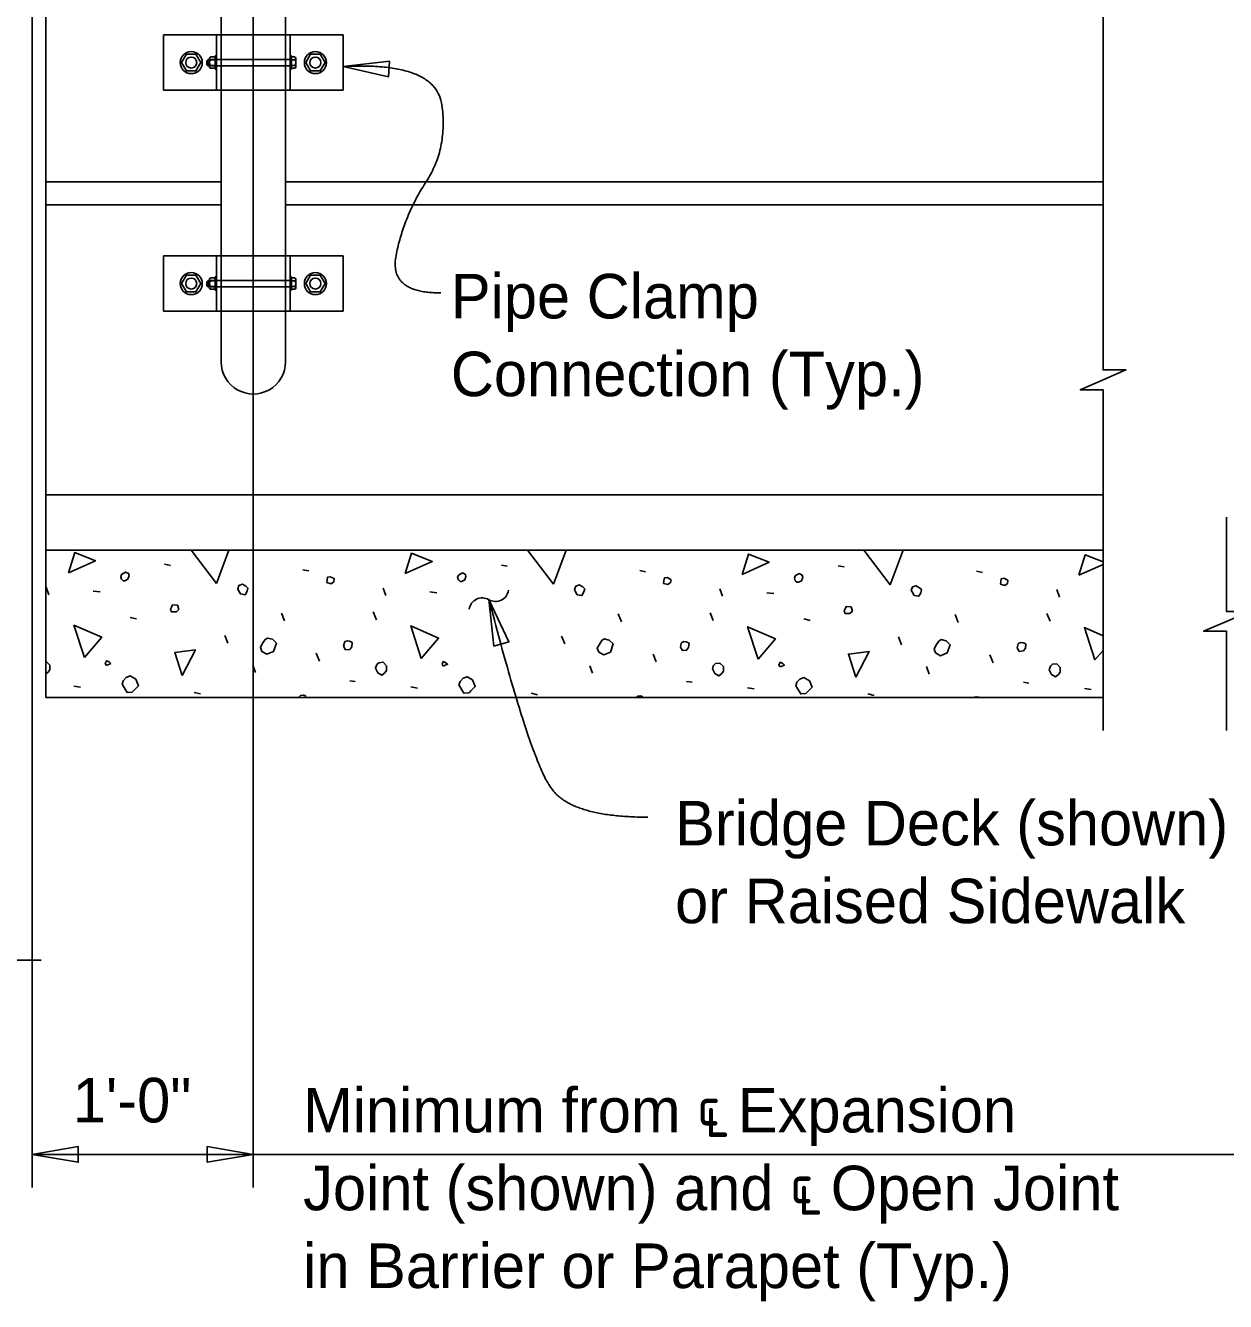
# Model space of a CAD drawing. Extents: x 0 to 41.1, y 0 to 25.9.
# Drawn here: x 23.58 to 29.01, y 11.16 to 16.93 of the extents above; entities that cross this region are included whole.
import ezdxf

# ---------------------------------------------------------------- set-up
doc = ezdxf.new("R2010")
doc.units = 0
for name, color, linetype in [('CL_Major', 7, 'Continuous'), ('Dimension', 7, 'Continuous'), ('Miscellaneous', 7, 'Continuous'), ('SteelMisc', 7, 'Continuous'), ('SteelMisc_h', 7, 'Continuous'), ('SupstrConc', 7, 'Continuous'), ('SupstrConc_h', 7, 'Continuous'), ('TextStructures', 7, 'Continuous')]:
    doc.layers.add(name, color=color, linetype=linetype)

msp = doc.modelspace()

# ---------------------------------------------------------------- linework, layer by layer
at = {"layer": 'CL_Major'}
for p, q in [((24.6151, 11.6734), (24.6151, 25.0052)), ((23.6151, 11.6734), (23.6151, 17.2313))]:
    msp.add_line(p, q, dxfattribs=at)
at = {"layer": 'Dimension'}
msp.add_line((23.6151, 11.8234), (29.4153, 11.8234), dxfattribs=at)
for points in [[(28.4596, 17.2246), (28.4596, 15.3737), (28.5629, 15.3737), (28.4596, 15.3287), (28.3562, 15.2837), (28.4596, 15.2837), (28.4596, 13.7412)], [(29.0176, 14.7079), (29.0176, 14.2808), (29.1209, 14.2808), (29.0176, 14.2358), (28.9142, 14.1908), (29.0176, 14.1908), (29.0176, 13.7412)], [(23.6547, 12.7032), (22.9577, 12.7032), (22.9577, 12.587), (22.8583, 12.812), (22.8583, 12.7032), (22.2031, 12.7032)]]:
    msp.add_lwpolyline(points, dxfattribs=at)
for points in [[(25.0211, 16.7461), (25.2271, 16.6998), (25.2309, 16.7703)], [(25.6811, 14.3341), (25.7034, 14.1241), (25.7713, 14.1431)], [(23.6151, 11.8235), (23.8234, 11.7882), (23.8234, 11.8588)], [(24.6151, 11.8235), (24.4069, 11.8588), (24.4069, 11.7882)]]:
    msp.add_lwpolyline(points, close=True, dxfattribs=at)
for centre, start, end in [((25.6504, 14.2822), 59.84335, 171.57057), ((25.7103, 14.3853), 239.84335, 351.57057)]:
    msp.add_arc(centre, 0.0596, start, end, dxfattribs=at)
for points in [[(25.4627, 15.7225), (25.2257, 15.7202), (25.2971, 16.0714), (25.4956, 16.3764), (25.4402, 16.7692), (25.021, 16.7461)], [(26.3997, 13.3497), (26.0593, 13.3497), (25.8702, 13.6052), (25.6811, 14.334)]]:
    msp.add_open_spline(points, degree=2, dxfattribs=at)
at = {"layer": 'Miscellaneous'}
for p, q in [((24.4075, 16.7575), (24.4075, 16.7696)), ((24.4132, 16.7575), (24.4132, 16.7696)), ((24.4075, 15.7575), (24.4075, 15.7696)), ((24.4132, 15.7575), (24.4132, 15.7696)), ((24.2137, 14.4942), (24.2402, 14.4889)), ((24.8395, 14.4694), (24.866, 14.4641)), ((25.7375, 14.4907), (25.7641, 14.4854)), ((26.3633, 14.4659), (26.3898, 14.4606)), ((27.2613, 14.4871), (27.2879, 14.4818)), ((27.8871, 14.4624), (27.9137, 14.4571)), ((23.6905, 14.3563), (23.6781, 14.3899)), ((25.2143, 14.3528), (25.2019, 14.3864)), ((26.7381, 14.3492), (26.7257, 14.3828)), ((28.2619, 14.3457), (28.2495, 14.3793)), ((23.8902, 14.3722), (23.922, 14.3687)), ((25.414, 14.3687), (25.4459, 14.3651)), ((26.9378, 14.3651), (26.9697, 14.3616)), ((24.7564, 14.2379), (24.7423, 14.2732)), ((25.1718, 14.2432), (25.1577, 14.2785)), ((26.2802, 14.2343), (26.2661, 14.2697)), ((26.6957, 14.2396), (26.6815, 14.275)), ((27.8041, 14.2308), (27.7899, 14.2661)), ((28.2195, 14.2361), (28.2053, 14.2715)), ((24.0582, 14.2538), (24.0864, 14.2467)), ((27.1058, 14.2467), (27.1341, 14.2396)), ((24.5001, 14.1371), (24.486, 14.1725)), ((26.0239, 14.1336), (26.0098, 14.1689)), ((27.5477, 14.13), (27.5336, 14.1654)), ((24.9138, 14.0558), (24.8996, 14.0911)), ((24.6256, 14.0045), (24.6132, 14.0381)), ((26.1494, 14.001), (26.137, 14.0346)), ((26.4376, 14.0522), (26.4234, 14.0876)), ((27.6732, 13.9974), (27.6609, 14.031)), ((27.9614, 14.0487), (27.9472, 14.0841)), ((23.8036, 13.9426), (23.8336, 13.9373)), ((25.0516, 13.9674), (25.0764, 13.9639)), ((25.3274, 13.9391), (25.3575, 13.9338)), ((26.5755, 13.9639), (26.6002, 13.9603)), ((26.8512, 13.9356), (26.8813, 13.9303)), ((28.0993, 13.9603), (28.124, 13.9568)), ((28.375, 13.932), (28.4051, 13.9267)), ((24.3481, 13.9144), (24.3764, 13.9073)), ((25.8719, 13.9108), (25.9002, 13.9038)), ((27.3957, 13.9073), (27.424, 13.9002))]:
    msp.add_line(p, q, dxfattribs=at)
for points in [[(24.4488, 14.4076), (24.3346, 14.5578)], [(24.505, 14.5578), (24.4488, 14.4076)], [(25.9726, 14.404), (25.8558, 14.5578)], [(26.0301, 14.5578), (25.9726, 14.404)], [(27.4965, 14.4005), (27.3769, 14.5578)], [(27.5553, 14.5578), (27.4965, 14.4005)], [(23.7788, 14.4553), (23.8071, 14.5472), (23.9008, 14.5101), (23.7788, 14.4553)], [(25.3027, 14.4518), (25.3309, 14.5437), (25.4246, 14.5066), (25.3027, 14.4518)], [(26.8265, 14.4482), (26.8548, 14.5402), (26.9485, 14.503), (26.8265, 14.4482)], [(28.3503, 14.4447), (28.3786, 14.5366), (28.4595, 14.5045)], [(28.4595, 14.4938), (28.3503, 14.4447)], [(24.0263, 14.4199), (24.0334, 14.4199), (24.0475, 14.427), (24.0529, 14.4429), (24.0511, 14.4518), (24.0369, 14.4588), (24.0193, 14.4482), (24.0157, 14.4376), (24.0193, 14.427), (24.0263, 14.4199)], [(24.9473, 14.4111), (24.9668, 14.4058), (24.9792, 14.4146), (24.9809, 14.427), (24.9774, 14.4306), (24.9633, 14.4376), (24.9509, 14.4359), (24.9491, 14.4235), (24.9473, 14.4111)], [(25.5502, 14.4164), (25.5572, 14.4164), (25.5714, 14.4235), (25.5767, 14.4394), (25.5749, 14.4482), (25.5608, 14.4553), (25.5431, 14.4447), (25.5395, 14.4341), (25.5431, 14.4235), (25.5502, 14.4164)], [(27.074, 14.4129), (27.081, 14.4129), (27.0952, 14.4199), (27.1005, 14.4359), (27.0987, 14.4447), (27.0846, 14.4518), (27.0669, 14.4412), (27.0634, 14.4306), (27.0669, 14.4199), (27.074, 14.4129)], [(24.5478, 14.3757), (24.5567, 14.3598), (24.5779, 14.3563), (24.5867, 14.3722), (24.5903, 14.3864), (24.5814, 14.3952), (24.5655, 14.404), (24.5496, 14.3987), (24.5443, 14.3828), (24.5478, 14.3757)], [(26.0716, 14.3722), (26.0805, 14.3563), (26.1017, 14.3528), (26.1105, 14.3687), (26.1141, 14.3828), (26.1052, 14.3917), (26.0893, 14.4005), (26.0734, 14.3952), (26.0681, 14.3793), (26.0716, 14.3722)], [(26.4712, 14.4076), (26.4906, 14.4023), (26.503, 14.4111), (26.5047, 14.4235), (26.5012, 14.427), (26.4871, 14.4341), (26.4747, 14.4323), (26.4729, 14.4199), (26.4712, 14.4076)], [(27.5955, 14.3687), (27.6043, 14.3528), (27.6255, 14.3492), (27.6343, 14.3651), (27.6379, 14.3793), (27.629, 14.3881), (27.6131, 14.397), (27.5972, 14.3917), (27.5919, 14.3757), (27.5955, 14.3687)], [(27.995, 14.404), (28.0144, 14.3987), (28.0268, 14.4076), (28.0286, 14.4199), (28.025, 14.4235), (28.0109, 14.4306), (27.9985, 14.4288), (27.9967, 14.4164), (27.995, 14.404)], [(24.2455, 14.2785), (24.2668, 14.2785), (24.2774, 14.2891), (24.2721, 14.3086), (24.2491, 14.3103), (24.2455, 14.2997), (24.2402, 14.2909), (24.2455, 14.2785), (24.242, 14.2821)], [(27.2932, 14.2715), (27.3144, 14.2715), (27.325, 14.2821), (27.3197, 14.3015), (27.2967, 14.3033), (27.2932, 14.2927), (27.2879, 14.2838), (27.2932, 14.2715), (27.2896, 14.275)], [(23.8513, 14.0717), (23.8036, 14.2184), (23.9291, 14.1636), (23.8513, 14.0717)], [(25.3751, 14.0682), (25.3274, 14.2149), (25.4529, 14.1601), (25.3751, 14.0682)], [(26.899, 14.0646), (26.8512, 14.2113), (26.9767, 14.1565), (26.899, 14.0646)], [(28.4228, 14.0611), (28.375, 14.2078), (28.4595, 14.1709)], [(24.6539, 14.1), (24.6769, 14.0876), (24.7069, 14.1), (24.7193, 14.1371), (24.7016, 14.1548), (24.6786, 14.1601), (24.668, 14.153), (24.6557, 14.1336), (24.6468, 14.1177), (24.6539, 14.1)], [(25.0234, 14.123), (25.0322, 14.107), (25.0516, 14.1088), (25.0605, 14.1212), (25.0622, 14.1406), (25.0499, 14.1459), (25.041, 14.1477), (25.0304, 14.1442), (25.0269, 14.1406), (25.0234, 14.123)], [(26.1777, 14.0964), (26.2007, 14.0841), (26.2307, 14.0964), (26.2431, 14.1336), (26.2254, 14.1512), (26.2025, 14.1565), (26.1919, 14.1495), (26.1795, 14.13), (26.1706, 14.1141), (26.1777, 14.0964)], [(27.7015, 14.0929), (27.7245, 14.0805), (27.7546, 14.0929), (27.7669, 14.13), (27.7493, 14.1477), (27.7263, 14.153), (27.7157, 14.1459), (27.7033, 14.1265), (27.6945, 14.1106), (27.7015, 14.0929)], [(28.9269, 14.1963), (28.9241, 14.1908)], [(24.2933, 13.9904), (24.2597, 14.0947), (24.3534, 14.107), (24.2933, 13.9904)], [(26.5472, 14.1194), (26.556, 14.1035), (26.5755, 14.1053), (26.5843, 14.1177), (26.5861, 14.1371), (26.5737, 14.1424), (26.5648, 14.1442), (26.5542, 14.1406), (26.5507, 14.1371), (26.5472, 14.1194)], [(27.3409, 13.9833), (27.3073, 14.0876), (27.401, 14.1), (27.3409, 13.9833)], [(28.071, 14.1159), (28.0798, 14.1), (28.0993, 14.1017), (28.1081, 14.1141), (28.1099, 14.1336), (28.0975, 14.1389), (28.0887, 14.1406), (28.0781, 14.1371), (28.0745, 14.1336), (28.071, 14.1159)], [(28.4595, 14.1045), (28.4228, 14.0611)], [(23.6763, 13.9983), (23.6869, 14.0063), (23.694, 14.0169), (23.694, 14.0381), (23.6781, 14.054), (23.6763, 14.0539)], [(23.9503, 14.0363), (23.9698, 14.0452), (23.9627, 14.0522), (23.9503, 14.0576), (23.945, 14.0452), (23.9503, 14.0363)], [(25.1683, 14.024), (25.1789, 14.0028), (25.1966, 13.9921), (25.2107, 14.0028), (25.2178, 14.0134), (25.2178, 14.0346), (25.2019, 14.0505), (25.1825, 14.0487), (25.1736, 14.0399), (25.1683, 14.024)], [(25.4741, 14.0328), (25.4936, 14.0416), (25.4865, 14.0487), (25.4741, 14.054), (25.4688, 14.0416), (25.4741, 14.0328)], [(26.6921, 14.0204), (26.7027, 13.9992), (26.7204, 13.9886), (26.7346, 13.9992), (26.7416, 14.0098), (26.7416, 14.031), (26.7257, 14.0469), (26.7063, 14.0452), (26.6974, 14.0363), (26.6921, 14.0204)], [(26.998, 14.0293), (27.0174, 14.0381), (27.0103, 14.0452), (26.998, 14.0505), (26.9926, 14.0381), (26.998, 14.0293)], [(28.2159, 14.0169), (28.2266, 13.9957), (28.2442, 13.9851), (28.2584, 13.9957), (28.2654, 14.0063), (28.2654, 14.0275), (28.2495, 14.0434), (28.2301, 14.0416), (28.2212, 14.0328), (28.2159, 14.0169)], [(24.021, 13.9515), (24.044, 13.9144), (24.067, 13.9161), (24.0758, 13.925), (24.0953, 13.9444), (24.0829, 13.9745), (24.0582, 13.9886), (24.0405, 13.9815), (24.0263, 13.9674), (24.021, 13.9515)], [(25.5448, 13.948), (25.5678, 13.9108), (25.5908, 13.9126), (25.5996, 13.9214), (25.6191, 13.9409), (25.6067, 13.9709), (25.582, 13.9851), (25.5643, 13.978), (25.5502, 13.9639), (25.5448, 13.948)], [(27.0687, 13.9444), (27.0916, 13.9073), (27.1146, 13.9091), (27.1235, 13.9179), (27.1429, 13.9373), (27.1305, 13.9674), (27.1058, 13.9815), (27.0881, 13.9745), (27.074, 13.9603), (27.0687, 13.9444)], [(24.8519, 13.8912), (24.8501, 13.9002), (24.8413, 13.902), (24.8289, 13.9002), (24.8198, 13.8912)], [(26.375, 13.8912), (26.3739, 13.8967), (26.3651, 13.8985), (26.3527, 13.8967), (26.3472, 13.8912)], [(27.8981, 13.8912), (27.8977, 13.8931), (27.8889, 13.8949), (27.8765, 13.8931), (27.8745, 13.8912)]]:
    msp.add_lwpolyline(points, dxfattribs=at)
at = {"layer": 'SteelMisc'}
for p, q in [((24.4692, 16.8894), (24.4692, 23.2644)), ((24.7609, 16.8894), (24.7609, 23.2644)), ((24.2091, 16.8894), (25.021, 16.8894)), ((24.2091, 16.6394), (24.2091, 16.8894)), ((24.4484, 16.8894), (24.4484, 16.6394)), ((24.7817, 16.8894), (24.7817, 16.6394)), ((25.021, 16.8894), (25.021, 16.6394)), ((24.4047, 16.7724), (24.4103, 16.7789)), ((24.4047, 16.7547), (24.4047, 16.7724)), ((24.4047, 16.7547), (24.4103, 16.749)), ((24.4103, 16.7789), (24.4168, 16.7789)), ((24.4103, 16.749), (24.4103, 16.7789)), ((24.4103, 16.749), (24.4168, 16.749)), ((24.4168, 16.7823), (24.4168, 16.7465)), ((24.4215, 16.7774), (24.4418, 16.7774)), ((24.4215, 16.7514), (24.4418, 16.7514)), ((24.4217, 16.7904), (24.4418, 16.7904)), ((24.4418, 16.7947), (24.4418, 16.734)), ((24.4418, 16.7947), (24.4484, 16.7947)), ((24.4418, 16.7904), (24.4418, 16.7384)), ((24.788, 16.7947), (24.782, 16.7947)), ((24.788, 16.7947), (24.788, 16.734)), ((24.8027, 16.7903), (24.788, 16.7903)), ((24.8028, 16.7773), (24.788, 16.7773)), ((24.8028, 16.7514), (24.788, 16.7514)), ((24.8078, 16.745), (24.8078, 16.7838)), ((24.4218, 16.7384), (24.4418, 16.7384)), ((24.4418, 16.734), (24.4484, 16.734)), ((24.788, 16.734), (24.782, 16.734)), ((24.8027, 16.7384), (24.788, 16.7384)), ((25.021, 16.6394), (24.2091, 16.6394)), ((24.4692, 16.6394), (24.4692, 15.8894)), ((24.7609, 16.6394), (24.7609, 15.8894)), ((24.2091, 15.8894), (25.021, 15.8894)), ((24.2091, 15.6394), (24.2091, 15.8894)), ((24.4484, 15.8894), (24.4484, 15.6394)), ((24.7817, 15.8894), (24.7817, 15.6394)), ((25.021, 15.8894), (25.021, 15.6394)), ((24.4047, 15.7724), (24.4103, 15.7789)), ((24.4047, 15.7547), (24.4047, 15.7724)), ((24.4103, 15.7789), (24.4168, 15.7789)), ((24.4103, 15.749), (24.4103, 15.7789)), ((24.4168, 15.7823), (24.4168, 15.7465)), ((24.4215, 15.7774), (24.4418, 15.7774)), ((24.4217, 15.7904), (24.4418, 15.7904)), ((24.4418, 15.7947), (24.4418, 15.734)), ((24.4418, 15.7947), (24.4484, 15.7947)), ((24.4418, 15.7904), (24.4418, 15.7384)), ((24.788, 15.7947), (24.782, 15.7947)), ((24.788, 15.7947), (24.788, 15.734)), ((24.8027, 15.7903), (24.788, 15.7903)), ((24.8028, 15.7773), (24.788, 15.7773)), ((24.8078, 15.745), (24.8078, 15.7838)), ((24.4047, 15.7547), (24.4103, 15.749)), ((24.4103, 15.749), (24.4168, 15.749)), ((24.4215, 15.7514), (24.4418, 15.7514)), ((24.4218, 15.7384), (24.4418, 15.7384)), ((24.4418, 15.734), (24.4484, 15.734)), ((24.788, 15.734), (24.782, 15.734)), ((24.8028, 15.7514), (24.788, 15.7514)), ((24.8027, 15.7384), (24.788, 15.7384)), ((25.021, 15.6394), (24.2091, 15.6394)), ((24.4692, 15.6394), (24.4692, 15.4102)), ((24.7609, 15.4102), (24.7609, 15.6394))]:
    msp.add_line(p, q, dxfattribs=at)
for points in [[(24.3124, 16.8019), (24.3557, 16.8019), (24.3774, 16.7644), (24.3557, 16.7269), (24.3124, 16.7269), (24.2907, 16.7644)], [(24.8744, 16.8019), (24.9177, 16.8019), (24.9394, 16.7644), (24.9177, 16.7269), (24.8744, 16.7269), (24.8527, 16.7644)], [(24.3124, 15.8019), (24.3557, 15.8019), (24.3774, 15.7644), (24.3557, 15.7269), (24.3124, 15.7269), (24.2907, 15.7644)], [(24.8744, 15.8019), (24.9177, 15.8019), (24.9394, 15.7644), (24.9177, 15.7269), (24.8744, 15.7269), (24.8527, 15.7644)]]:
    msp.add_lwpolyline(points, close=True, dxfattribs=at)
for centre, radius in [((24.3341, 16.7644), 0.05), ((24.896, 16.7644), 0.05), ((24.3341, 16.7644), 0.025), ((24.896, 16.7644), 0.025), ((24.3341, 15.7644), 0.05), ((24.3341, 15.7644), 0.025), ((24.896, 15.7644), 0.05), ((24.896, 15.7644), 0.025)]:
    msp.add_circle(centre, radius, dxfattribs=at)
for centre, radius, start, end in [((24.4234, 16.7838), 0.00674, 104.48908, 254.18889), ((24.4363, 16.7644), 0.0196, 138.62797, 221.37203), ((24.4234, 16.7449), 0.00673, 105.7823, 255.54039), ((24.801, 16.7838), 0.00673, 285.7823, 75.54039), ((24.801, 16.7449), 0.00674, 284.48908, 74.18889), ((24.7881, 16.7644), 0.0196, 318.62797, 41.37203), ((24.4234, 15.7838), 0.00674, 104.48908, 254.18889), ((24.4363, 15.7644), 0.0196, 138.62797, 221.37203), ((24.801, 15.7838), 0.00673, 285.7823, 75.54039), ((24.7881, 15.7644), 0.0196, 318.62797, 41.37203), ((24.4234, 15.7449), 0.00673, 105.7823, 255.54039), ((24.801, 15.7449), 0.00674, 284.48908, 74.18889)]:
    msp.add_arc(centre, radius, start, end, dxfattribs=at)
msp.add_ellipse((24.6151, 15.4102), major_axis=(0, 0.1458), ratio=0.999499, start_param=1.570796, end_param=4.712389, dxfattribs=at)
at = {"layer": 'SteelMisc_h'}
for p, q in [((24.4692, 16.8894), (24.4692, 16.6394)), ((24.7609, 16.8894), (24.7609, 16.6394)), ((24.7817, 16.7789), (24.4168, 16.7789)), ((24.4168, 16.749), (24.7817, 16.749)), ((24.4692, 15.8894), (24.4692, 15.6394)), ((24.7609, 15.8894), (24.7609, 15.6394)), ((24.7817, 15.7789), (24.4168, 15.7789)), ((24.4168, 15.749), (24.7817, 15.749))]:
    msp.add_line(p, q, dxfattribs=at)
at = {"layer": 'SupstrConc'}
for p, q in [((23.6763, 17.2245), (23.6763, 13.8912)), ((23.6763, 16.2245), (24.4692, 16.2245)), ((24.7609, 16.2245), (28.4595, 16.2245)), ((24.7609, 16.2245), (26.002, 16.2245)), ((23.6763, 16.1203), (24.4692, 16.1203)), ((24.7609, 16.1203), (28.4595, 16.1203)), ((24.7609, 16.1203), (26.002, 16.1203)), ((23.6763, 14.5578), (28.4595, 14.5578)), ((23.6763, 13.8912), (28.4595, 13.8912))]:
    msp.add_line(p, q, dxfattribs=at)
at = {"layer": 'SupstrConc_h'}
msp.add_line((23.6763, 14.8078), (28.4595, 14.8078), dxfattribs=at)

# ---------------------------------------------------------------- texts
at = {"layer": 'Dimension'}
for s, p in [('Pipe Clamp ', (25.5087, 15.6066)), ('Connection (Typ.)', (25.5087, 15.2546)), ('Bridge Deck (shown)', (26.5232, 13.222)), ('or Raised Sidewalk', (26.5232, 12.87)), ('Minimum from ℄ Expansion', (24.8405, 11.923)), ('Joint (shown) and ℄ Open Joint ', (24.8405, 11.571)), ('in Barrier or Parapet (Typ.)', (24.8405, 11.219))]:
    msp.add_text(s, height=0.2016, dxfattribs=at).set_placement(p)
at = {"layer": 'TextStructures'}
msp.add_text('1\'-0"', height=0.2016, dxfattribs=at).set_placement((23.7982, 11.9684))

doc.saveas('drawing.dxf')
